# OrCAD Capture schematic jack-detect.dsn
size A; title: Headphone Jack Detector
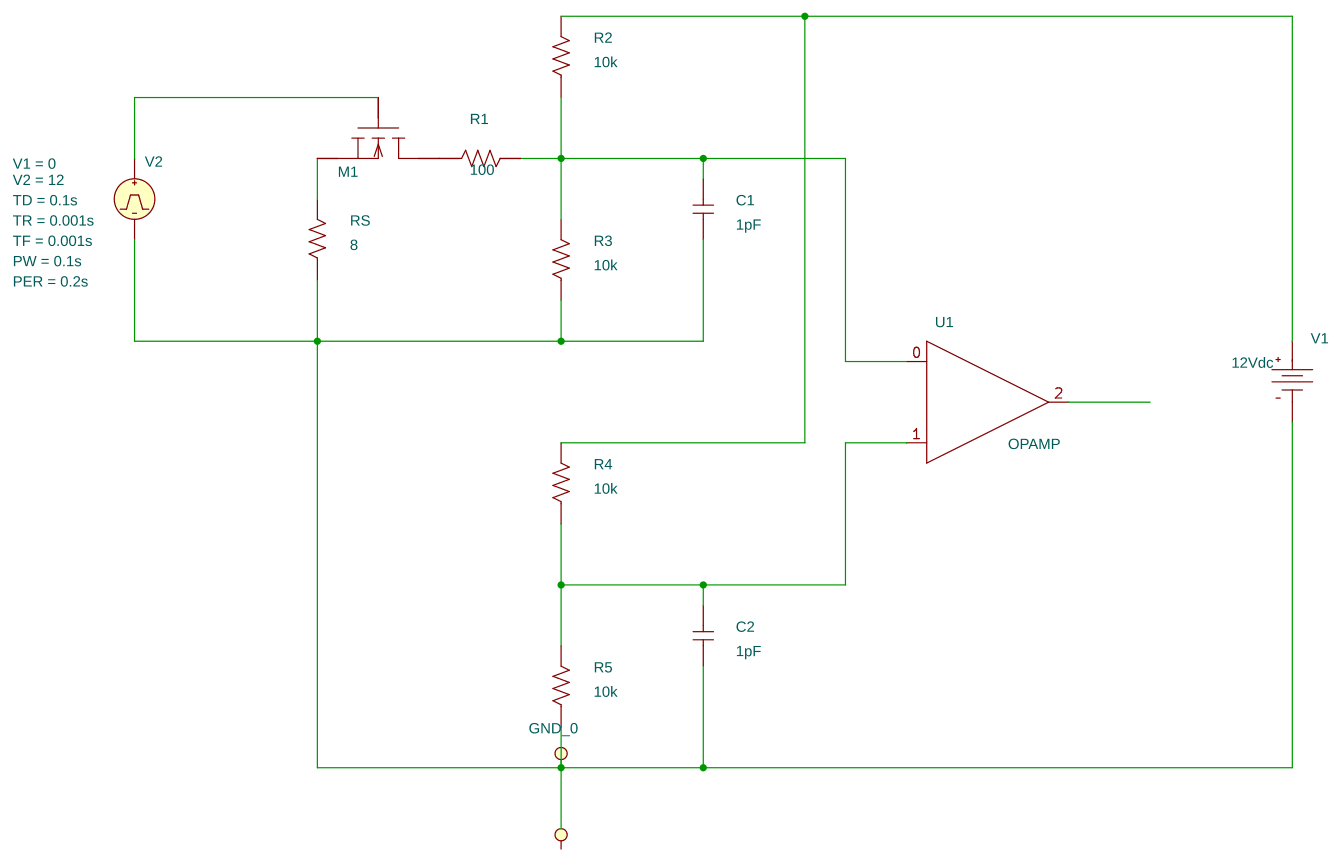
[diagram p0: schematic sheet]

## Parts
C1  1pF  [cap196]
C2  1pF  [cap196]
M1  MbreakN3
R1  100  [AXRC05]
R2  10k  [AXRC05]
R3  10k  [AXRC05]
R4  10k  [AXRC05]
R5  10k  [AXRC05]
RS  8  [AXRC05]
U1  OPAMP
V1  VDC
V2  VPULSE

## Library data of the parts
C1 C2 = C
M1 = MbreakN3
R1-R5 RS = R
U1 = OPAMP
V1 = VDC: DC: 12Vdc
V2 = VPULSE: PER: 0.2s; PW: 0.1s; TD: 0.1s; TF: 0.001s; TR: 0.001s; V1: 0; V2: 12

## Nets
0: C1.1 C2.1 R3.1 R5.1 RS.1 V1.1(-) V2.2(-)
N14390: M1.0(s) RS.2
N14397: C1.2 R1.2 R2.1 R3.2 U1.0(+)
N14566: C2.2 R4.1 R5.2 U1.1(-)
N14872: R2.2 R4.2 V1.0(+)
N15076: M1.1(g) V2.1(+)
N15664: M1.2(d) R1.1

Not connected (* = marked no-connect by the designer): U1 2(OUT)
